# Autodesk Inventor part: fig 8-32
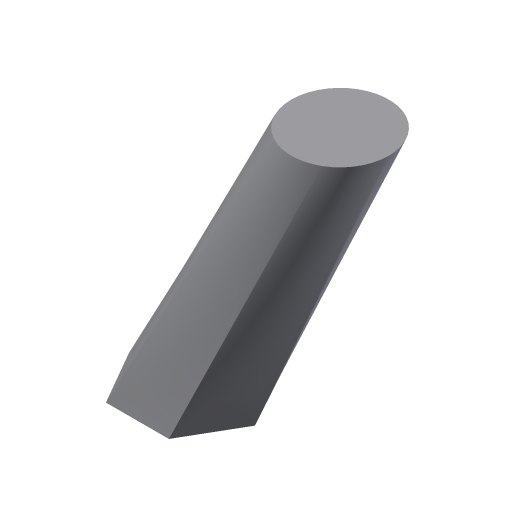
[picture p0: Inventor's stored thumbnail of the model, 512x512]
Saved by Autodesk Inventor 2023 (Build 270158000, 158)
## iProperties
Created: 2001-12
Part Number: fig 8-32
Document SubType Name: Modeling
Designer: CADSoft
Density: 1 g/cm^3
Material: Generic
Appearance: Default
Control State: 0
Master: False
Checked Out: False
Shininess: 77.0
Angle Display Precision: 2
Document Length Units: 11269
Document Angle Units: 11279
Document Time Units: 11290
Document Mass Units: 11283
Document Length Units Precision: 3
Document Angle Units Precision: 2
Density: 0.0
Volumn: 0.0
Area: 0.0
PropertySet Name: Model Information
Author: CADSoft
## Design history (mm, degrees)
workplane "Work Plane3"
workplane "Work Plane4"
sketch "Sketch12"
  geometry: L1 (0, 10.598)-(9.178, -5.299); L2 (9.178, -5.299)-(-9.178, -5.299); L3 (-9.178, -5.299)-(0, 10.598); 1 further point
  constraints: 6 end point, 5 other
workplane "Work Plane5"
workplane "Work Plane6"
workplane "Work Plane7"
sketch "Sketch16"
  geometry: A1 r 72.799 centre (23.007, 110.594) between (0, 41.527) and (70, 54.995); 1 further point
  constraints: 2 point on circle, 1 centre point
loft "Loft5" dims "d57" = 0, "d58" = 90 deg, "d59" = 0, "d60" = 90 deg
body "Solid2"
sketch "Sketch1"
  geometry: L1 (19.387, 0)-(9.693, -16.79); L2 (9.693, -16.79)-(-9.693, -16.79); L3 (-9.693, -16.79)-(-19.387, 0); L4 (-19.387, 0)-(-9.693, 16.79); L5 (-9.693, 16.79)-(9.693, 16.79); L6 (9.693, 16.79)-(19.387, 0); 1 further point
  constraints: 12 end point, 11 other
sketch "Sketch2"
  geometry: C1 r 15 at (23.06, 22.535)
  constraints: 1 centre point
